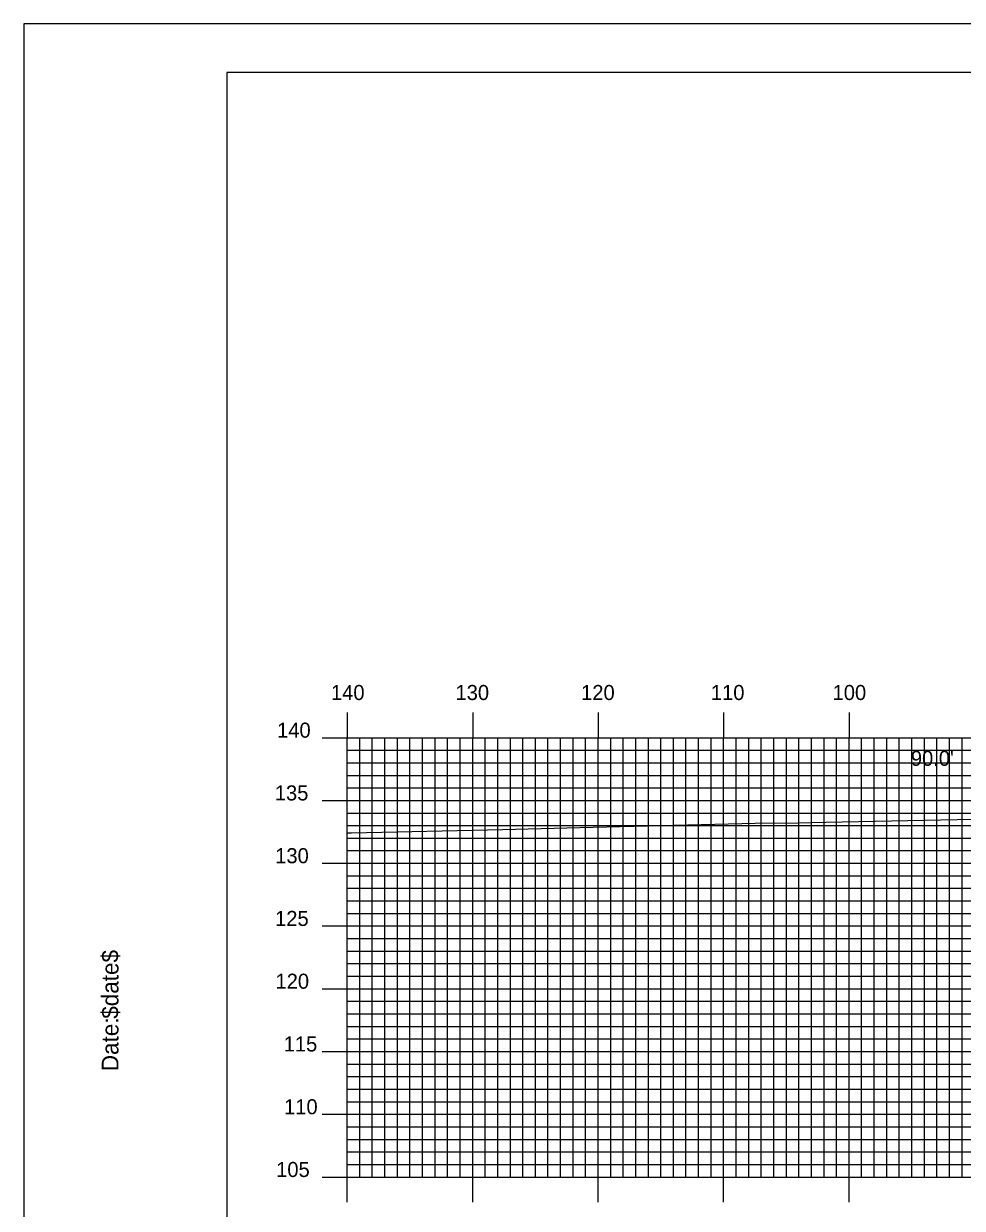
# Model space of a CAD drawing. Extents: x 1767694 to 1768037, y 442591 to 442811.
# Drawn here: x 1767693.7 to 1767768.5, y 442716.2 to 442810.5 of the extents above; entities that cross this region are included whole.
import ezdxf

# ---------------------------------------------------------------- set-up
doc = ezdxf.new("R2010")
doc.units = 0
for name, color, linetype in [('BORDER', 7, 'Continuous'), ('D_Text_Standard', 7, 'Continuous'), ('H_V ANNOTATION', 7, 'Continuous'), ('MAJOR', 7, 'Continuous'), ('MINOR', 7, 'Continuous'), ('PLOT BOUNDARY', 7, 'Continuous'), ('S_Roadway_Centerline', 7, 'Continuous')]:
    doc.layers.add(name, color=color, linetype=linetype)

msp = doc.modelspace()

# ---------------------------------------------------------------- linework, layer by layer
at = {"layer": 'BORDER'}
msp.add_lwpolyline([(1767709.85, 442596.665), (1768029.85, 442596.665), (1768029.85, 442806.665), (1767709.85, 442806.665)], close=True, dxfattribs=at)
at = {"layer": 'MAJOR'}
for p, q in [((1767719.45, 442755.669), (1767719.45, 442753.665)), ((1767729.45, 442755.669), (1767729.45, 442753.665)), ((1767739.45, 442755.669), (1767739.45, 442753.665)), ((1767749.45, 442755.669), (1767749.45, 442753.665)), ((1767759.45, 442755.669), (1767759.45, 442753.665)), ((1767717.446, 442753.665), (1767719.45, 442753.665)), ((1767719.45, 442753.665), (1767999.45, 442753.665)), ((1767719.45, 442718.665), (1767719.45, 442753.665)), ((1767719.45, 442718.665), (1767719.45, 442753.665)), ((1767719.45, 442753.665), (1767999.45, 442753.665)), ((1767729.45, 442718.665), (1767729.45, 442753.665)), ((1767739.45, 442718.665), (1767739.45, 442753.665)), ((1767749.45, 442718.665), (1767749.45, 442753.665)), ((1767759.45, 442718.665), (1767759.45, 442753.665)), ((1767717.446, 442748.665), (1767719.45, 442748.665)), ((1767719.45, 442748.665), (1767999.45, 442748.665)), ((1767717.446, 442743.665), (1767719.45, 442743.665)), ((1767719.45, 442743.665), (1767999.45, 442743.665)), ((1767717.446, 442738.665), (1767719.45, 442738.665)), ((1767719.45, 442738.665), (1767999.45, 442738.665)), ((1767717.446, 442733.665), (1767719.45, 442733.665)), ((1767719.45, 442733.665), (1767999.45, 442733.665)), ((1767717.446, 442728.665), (1767719.45, 442728.665)), ((1767719.45, 442728.665), (1767999.45, 442728.665)), ((1767717.446, 442723.665), (1767719.45, 442723.665)), ((1767719.45, 442723.665), (1767999.45, 442723.665)), ((1767717.446, 442718.665), (1767719.45, 442718.665)), ((1767719.45, 442718.665), (1767999.45, 442718.665)), ((1767719.45, 442718.665), (1767999.45, 442718.665)), ((1767719.45, 442716.661), (1767719.45, 442718.665)), ((1767729.45, 442716.661), (1767729.45, 442718.665)), ((1767739.45, 442716.661), (1767739.45, 442718.665)), ((1767749.45, 442716.661), (1767749.45, 442718.665)), ((1767759.45, 442716.661), (1767759.45, 442718.665))]:
    msp.add_line(p, q, dxfattribs=at)
at = {"layer": 'MINOR'}
for p, q in [((1767720.45, 442718.665), (1767720.45, 442753.665)), ((1767721.45, 442718.665), (1767721.45, 442753.665)), ((1767722.45, 442718.665), (1767722.45, 442753.665)), ((1767723.45, 442718.665), (1767723.45, 442753.665)), ((1767724.45, 442718.665), (1767724.45, 442753.665)), ((1767725.45, 442718.665), (1767725.45, 442753.665)), ((1767726.45, 442718.665), (1767726.45, 442753.665)), ((1767727.45, 442718.665), (1767727.45, 442753.665)), ((1767728.45, 442718.665), (1767728.45, 442753.665)), ((1767730.45, 442718.665), (1767730.45, 442753.665)), ((1767731.45, 442718.665), (1767731.45, 442753.665)), ((1767732.45, 442718.665), (1767732.45, 442753.665)), ((1767733.45, 442718.665), (1767733.45, 442753.665)), ((1767734.45, 442718.665), (1767734.45, 442753.665)), ((1767735.45, 442718.665), (1767735.45, 442753.665)), ((1767736.45, 442718.665), (1767736.45, 442753.665)), ((1767737.45, 442718.665), (1767737.45, 442753.665)), ((1767738.45, 442718.665), (1767738.45, 442753.665)), ((1767740.45, 442718.665), (1767740.45, 442753.665)), ((1767741.45, 442718.665), (1767741.45, 442753.665)), ((1767742.45, 442718.665), (1767742.45, 442753.665)), ((1767743.45, 442718.665), (1767743.45, 442753.665)), ((1767744.45, 442718.665), (1767744.45, 442753.665)), ((1767745.45, 442718.665), (1767745.45, 442753.665)), ((1767746.45, 442718.665), (1767746.45, 442753.665)), ((1767747.45, 442718.665), (1767747.45, 442753.665)), ((1767748.45, 442718.665), (1767748.45, 442753.665)), ((1767750.45, 442718.665), (1767750.45, 442753.665)), ((1767751.45, 442718.665), (1767751.45, 442753.665)), ((1767752.45, 442718.665), (1767752.45, 442753.665)), ((1767753.45, 442718.665), (1767753.45, 442753.665)), ((1767754.45, 442718.665), (1767754.45, 442753.665)), ((1767755.45, 442718.665), (1767755.45, 442753.665)), ((1767756.45, 442718.665), (1767756.45, 442753.665)), ((1767757.45, 442718.665), (1767757.45, 442753.665)), ((1767758.45, 442718.665), (1767758.45, 442753.665)), ((1767760.45, 442718.665), (1767760.45, 442753.665)), ((1767761.45, 442718.665), (1767761.45, 442753.665)), ((1767762.45, 442718.665), (1767762.45, 442753.665)), ((1767763.45, 442718.665), (1767763.45, 442753.665)), ((1767764.45, 442718.665), (1767764.45, 442753.665)), ((1767765.45, 442718.665), (1767765.45, 442753.665)), ((1767766.45, 442718.665), (1767766.45, 442753.665)), ((1767767.45, 442718.665), (1767767.45, 442753.665)), ((1767768.45, 442718.665), (1767768.45, 442753.665)), ((1767719.45, 442752.665), (1767999.45, 442752.665)), ((1767719.45, 442752.665), (1767721.454, 442752.665)), ((1767719.45, 442751.665), (1767999.45, 442751.665)), ((1767719.45, 442751.665), (1767721.454, 442751.665)), ((1767719.45, 442750.665), (1767999.45, 442750.665)), ((1767719.45, 442750.665), (1767721.454, 442750.665)), ((1767719.45, 442749.665), (1767999.45, 442749.665)), ((1767719.45, 442749.665), (1767721.454, 442749.665)), ((1767719.45, 442747.665), (1767999.45, 442747.665)), ((1767719.45, 442747.665), (1767721.454, 442747.665)), ((1767719.45, 442746.665), (1767999.45, 442746.665)), ((1767719.45, 442746.665), (1767721.454, 442746.665)), ((1767719.45, 442745.665), (1767999.45, 442745.665)), ((1767719.45, 442745.665), (1767721.454, 442745.665)), ((1767719.45, 442744.665), (1767999.45, 442744.665)), ((1767719.45, 442744.665), (1767721.454, 442744.665)), ((1767719.45, 442742.665), (1767999.45, 442742.665)), ((1767719.45, 442742.665), (1767721.454, 442742.665)), ((1767719.45, 442741.665), (1767999.45, 442741.665)), ((1767719.45, 442741.665), (1767721.454, 442741.665)), ((1767719.45, 442740.665), (1767999.45, 442740.665)), ((1767719.45, 442740.665), (1767721.454, 442740.665)), ((1767719.45, 442739.665), (1767999.45, 442739.665)), ((1767719.45, 442739.665), (1767721.454, 442739.665)), ((1767719.45, 442737.665), (1767999.45, 442737.665)), ((1767719.45, 442737.665), (1767721.454, 442737.665)), ((1767719.45, 442736.665), (1767999.45, 442736.665)), ((1767719.45, 442736.665), (1767721.454, 442736.665)), ((1767719.45, 442735.665), (1767999.45, 442735.665)), ((1767719.45, 442735.665), (1767721.454, 442735.665)), ((1767719.45, 442734.665), (1767999.45, 442734.665)), ((1767719.45, 442734.665), (1767721.454, 442734.665)), ((1767719.45, 442732.665), (1767999.45, 442732.665)), ((1767719.45, 442732.665), (1767721.454, 442732.665)), ((1767719.45, 442731.665), (1767999.45, 442731.665)), ((1767719.45, 442731.665), (1767721.454, 442731.665)), ((1767719.45, 442730.665), (1767999.45, 442730.665)), ((1767719.45, 442730.665), (1767721.454, 442730.665)), ((1767719.45, 442729.665), (1767999.45, 442729.665)), ((1767719.45, 442729.665), (1767721.454, 442729.665)), ((1767719.45, 442727.665), (1767999.45, 442727.665)), ((1767719.45, 442727.665), (1767721.454, 442727.665)), ((1767719.45, 442726.665), (1767999.45, 442726.665)), ((1767719.45, 442726.665), (1767721.454, 442726.665)), ((1767719.45, 442725.665), (1767999.45, 442725.665)), ((1767719.45, 442725.665), (1767721.454, 442725.665)), ((1767719.45, 442724.665), (1767999.45, 442724.665)), ((1767719.45, 442724.665), (1767721.454, 442724.665)), ((1767719.45, 442722.665), (1767999.45, 442722.665)), ((1767719.45, 442722.665), (1767721.454, 442722.665)), ((1767719.45, 442721.665), (1767999.45, 442721.665)), ((1767719.45, 442721.665), (1767721.454, 442721.665)), ((1767719.45, 442720.665), (1767999.45, 442720.665)), ((1767719.45, 442720.665), (1767721.454, 442720.665)), ((1767719.45, 442719.665), (1767999.45, 442719.665)), ((1767719.45, 442719.665), (1767721.454, 442719.665))]:
    msp.add_line(p, q, dxfattribs=at)
at = {"layer": 'PLOT BOUNDARY'}
msp.add_lwpolyline([(1767693.663, 442590.547), (1768033.663, 442590.547), (1768033.663, 442810.547), (1767693.663, 442810.547)], close=True, dxfattribs=at)
at = {"layer": 'S_Roadway_Centerline'}
msp.add_lwpolyline([(1767719.45, 442746.087), (1767719.506, 442746.087), (1767719.802, 442746.094), (1767731.833, 442746.338), (1767737.977, 442746.503), (1767751.955, 442746.853), (1767755.358, 442746.894), (1767757.596, 442746.933), (1767768.075, 442747.158), (1767777.122, 442747.25)], dxfattribs=at)

# ---------------------------------------------------------------- texts
at = {"layer": 'BORDER'}
for s, p in [('$date$', (1767701.219, 442731.275)), ('Date:', (1767701.219, 442727.099))]:
    msp.add_text(s, height=1.3392, rotation=90, dxfattribs=at).set_placement(p)
at = {"layer": 'D_Text_Standard'}
msp.add_text("90.0'", height=1.2, dxfattribs=at).set_placement((1767764.37, 442751.421))
at = {"layer": 'H_V ANNOTATION'}
for s, p in [('140', (1767718.154, 442756.665)), ('130', (1767728.079, 442756.665)), ('120', (1767738.09, 442756.665)), ('110', (1767748.433, 442756.665)), ('100', (1767758.133, 442756.665)), ('140', (1767713.859, 442753.665)), ('135', (1767713.677, 442748.665)), ('130', (1767713.709, 442743.665)), ('125', (1767713.699, 442738.665)), ('120', (1767713.731, 442733.665)), ('115', (1767714.384, 442728.665)), ('110', (1767714.416, 442723.665)), ('105', (1767713.784, 442718.665))]:
    msp.add_text(s, height=1.2, dxfattribs=at).set_placement(p)
at = {"layer": 'MAJOR'}
msp.add_text('-', height=0.012, dxfattribs=at).set_placement((1767719.441, 442718.665))

doc.saveas('drawing.dxf')
